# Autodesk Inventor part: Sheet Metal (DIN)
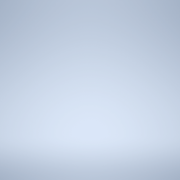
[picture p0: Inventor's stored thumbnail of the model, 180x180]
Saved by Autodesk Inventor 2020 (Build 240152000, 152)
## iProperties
Created: 2019-02
Part Number: Sheet Metal (DIN)
Material: Ogólny
Document SubType Name: Konstrukcja blachowa
Density: 1 g/cm^3
Sheet Metal Rule: Domyślny_mm
Appearance: Domyślna
Designer: F.Stasiak
Manager: www.cadconsulting.pl
Company: Fabian Stasiak CAD Consulting
Subject: Zbiór ćwiczeń. Autodesk Inventor 2020. Kurs podstawowy
Author: F.Stasiak
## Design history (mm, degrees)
other parameters: "Grubość" = 0.5 (derived), "WspółczynnikK" = 4.4, "PromieńGięcia" = 0.5 (= Grubość), "SzerokośćGięciaPodcięcia" = 0.5 (= Grubość), "GłębokośćGięciaPodcięcia" = 0.25 (= 0.5 x Grubość), "RozmiarPodcięciaNarożnika" = 2 (= 4 x Grubość), "OdstępPołączenia" = 0.01, "MinimalnaPozostałość" = 1 (= 2 x Grubość), "PromieńPrzejścia" = 0.5 (= PromieńGięcia), "Rozmiar_promienia_Jacobiego" = 0.5 (= PromieńGięcia), "Wielk_odstępu" = 0.5 (= Grubość)
